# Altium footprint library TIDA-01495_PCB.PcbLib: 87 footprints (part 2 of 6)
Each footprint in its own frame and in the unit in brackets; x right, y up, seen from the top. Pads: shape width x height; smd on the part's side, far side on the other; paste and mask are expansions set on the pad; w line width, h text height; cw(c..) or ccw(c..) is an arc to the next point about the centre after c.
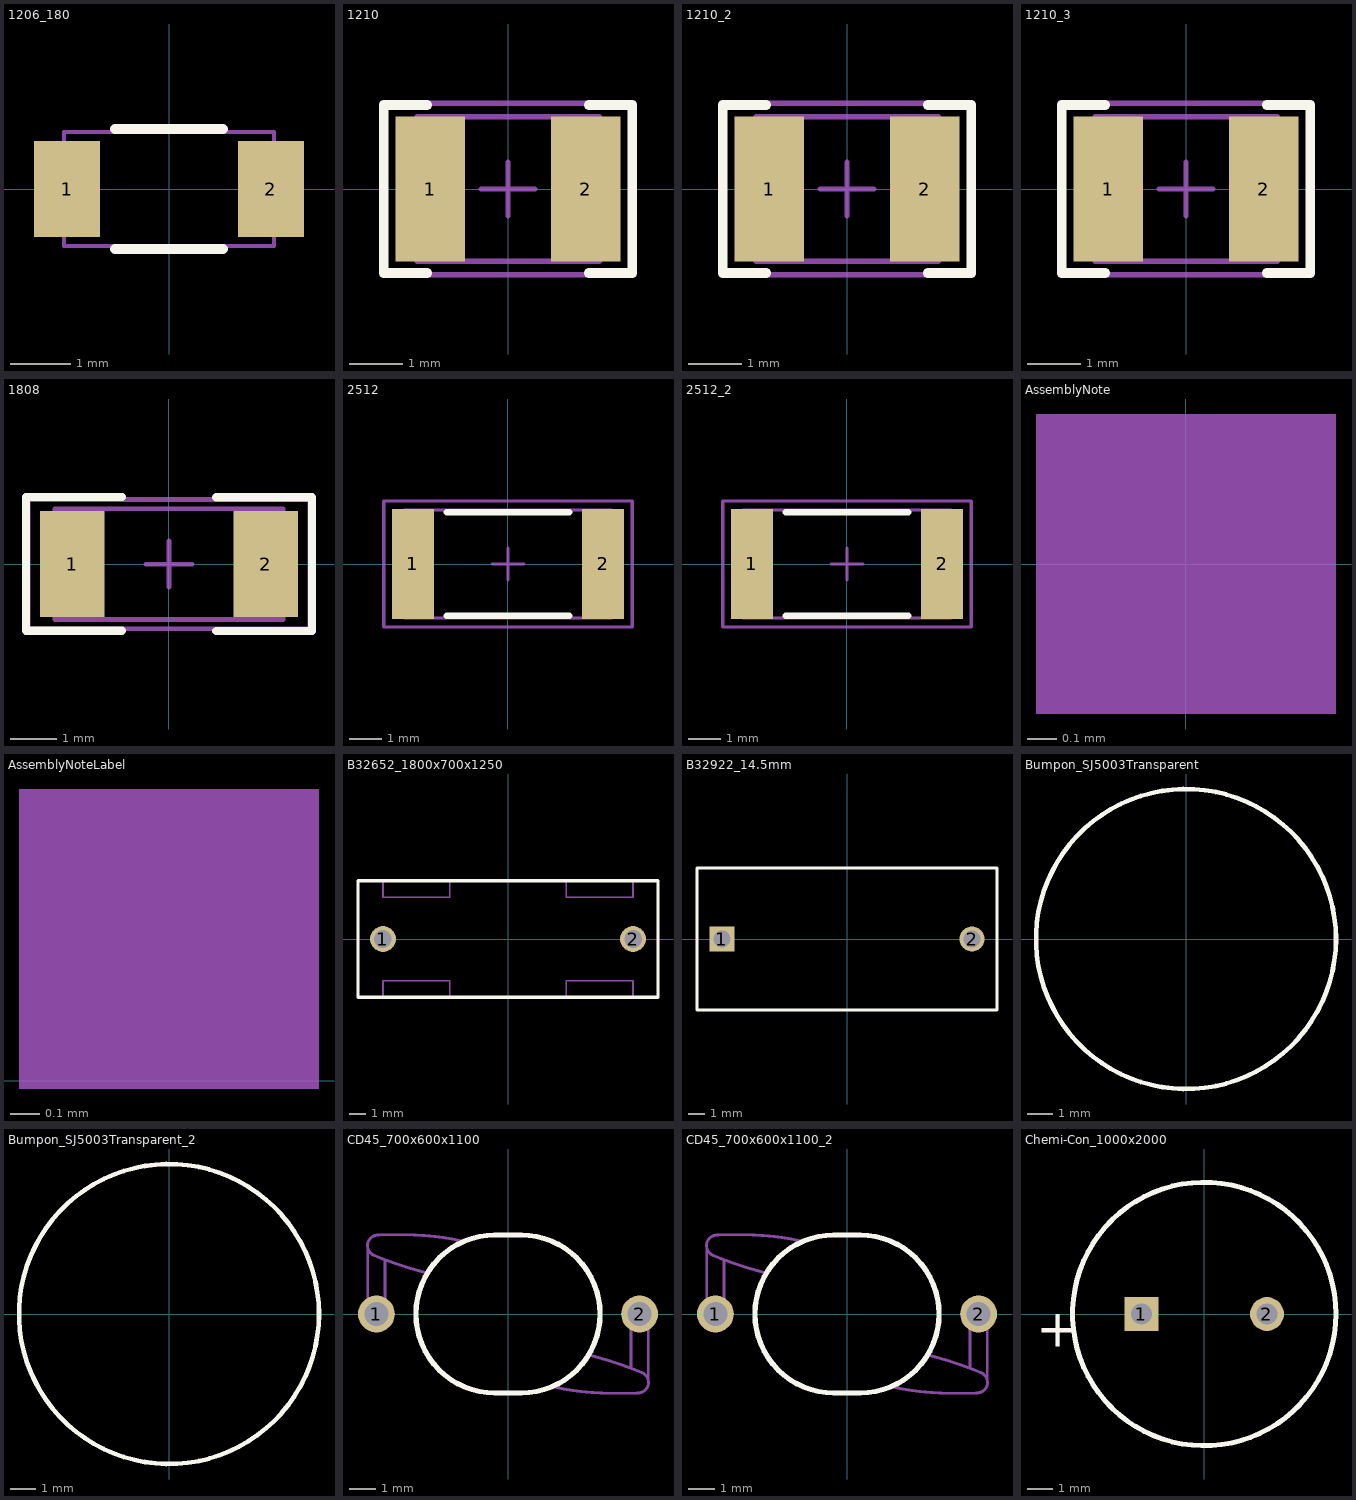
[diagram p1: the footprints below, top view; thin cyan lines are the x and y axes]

## 1206_180 [mm] "1206_180"
height 1.8
pads (2):
  rect 1.1x1.6 smd: 1(-1.7,0) 2(1.7,0)
Top Overlay:
  lines w0.17: -0.9,-1 0.9,-1 ; -0.9,1 0.9,1
Mechanical 5:
  lines w0.07: -1.75,-0.95 1.75,-0.95 1.75,0.95 -1.75,0.95 -1.75,-0.95
  text ".Designator" at 0.996,0.329 h0.81
3D body: height 1.8, standoff 0, extent -1.749,-0.949 -1.301,0.949
3D body: height 1.8, standoff 0, extent -1.299,-0.949 1.299,0.949
3D body: height 1.8, standoff 0, extent 1.301,-0.949 1.749,0.949

## 1210 [mm] "1210 from SM-752 data"
height 1.35
pads (2):
  rect 1.3x2.7 smd: 1(-1.45,0) 2(1.45,0)
Top Overlay:
  lines w0.178: -1.511,-1.568 -2.316,-1.568 -2.316,1.568 -1.511,1.568 ; 1.511,-1.568 2.316,-1.568 2.316,1.568 1.511,1.568
Mechanical 5:
  lines w0.1: -1.7,-1.35 -1.7,1.35 1.7,1.35 1.7,-1.35 -1.7,-1.35
  text ".Designator" at 1.198,0.346 h0.76
Mechanical 13:
  lines w0.1: -1.2,-1.35 -1.2,1.35 ; 1.2,-1.35 1.2,1.35 ; -1.7,-1.35 1.7,-1.35 1.7,1.35 -1.7,1.35 -1.7,-1.35
Mechanical 15:
  lines w0.1: -0.5,0 0.5,0 ; 0,-0.5 0,0.5 ; -2.35,-1.6 2.35,-1.6 2.35,1.6 -2.35,1.6 -2.35,-1.6
3D body: height 1.35, standoff 0, extent 1.201,-1.349 1.699,1.349
3D body: height 1.35, standoff 0, extent -1.199,-1.349 1.199,1.349
3D body: height 1.35, standoff 0, extent -1.699,-1.349 -1.201,1.349

## 1210_2 [mm]
pads (2):
  rect 1.3x2.7 smd: 1(-1.45,0) 2(1.45,0)
Top Overlay:
  lines w0.178: -1.511,-1.568 -2.316,-1.568 -2.316,1.568 -1.511,1.568 ; 1.511,-1.568 2.316,-1.568 2.316,1.568 1.511,1.568
Mechanical 5:
  lines w0.1: -1.7,-1.35 1.7,-1.35 1.7,1.35 -1.7,1.35 -1.7,-1.35
  text ".Designator" at 1.24,0.45 h0.76
Mechanical 13:
  lines w0.1: -1.2,-1.35 -1.2,1.35 ; 1.2,-1.35 1.2,1.35 ; -1.7,-1.35 -1.7,1.35 1.7,1.35 1.7,-1.35 -1.7,-1.35
Mechanical 15:
  lines w0.1: -0.5,0 0.5,0 ; 0,-0.5 0,0.5 ; -2.35,-1.6 -2.35,1.6 2.35,1.6 2.35,-1.6 -2.35,-1.6
3D body: height 1.35, standoff 0, extent -1.699,-1.349 -1.201,1.349
3D body: height 1.35, standoff 0, extent -1.199,-1.349 1.199,1.349
3D body: height 1.35, standoff 0, extent 1.201,-1.349 1.699,1.349

## 1210_3 [mm]
pads (2):
  rect 1.3x2.7 smd: 1(-1.45,0) 2(1.45,0)
Top Overlay:
  lines w0.178: -1.511,-1.568 -2.316,-1.568 -2.316,1.568 -1.511,1.568 ; 1.511,-1.568 2.316,-1.568 2.316,1.568 1.511,1.568
Mechanical 5:
  lines w0.1: -1.7,-1.35 1.7,-1.35 1.7,1.35 -1.7,1.35 -1.7,-1.35
  text ".Designator" at -1.177,-0.4 h0.89
Mechanical 13:
  lines w0.1: -1.2,-1.35 -1.2,1.35 ; 1.2,-1.35 1.2,1.35 ; -1.7,-1.35 -1.7,1.35 1.7,1.35 1.7,-1.35 -1.7,-1.35
Mechanical 15:
  lines w0.1: -0.5,0 0.5,0 ; 0,-0.5 0,0.5 ; -2.35,-1.6 -2.35,1.6 2.35,1.6 2.35,-1.6 -2.35,-1.6
3D body: height 1.35, standoff 0, extent -1.699,-1.349 -1.201,1.349
3D body: height 1.35, standoff 0, extent -1.199,-1.349 1.199,1.349
3D body: height 1.35, standoff 0, extent 1.201,-1.349 1.699,1.349

## 1808 [mm] "Chip Capacitor, Body 4.6x2.0mm, IPC Medium Density"
height 2.03
pads (2):
  rect 1.4x2.3 smd: 1(-2.1,0) 2(2.1,0)
Top Overlay:
  lines w0.178: -1.02,-1.445 -3.096,-1.445 -3.096,1.45 -1.02,1.45 ; 1.023,-1.448 3.099,-1.448 3.099,1.448 1.023,1.448
Mechanical 5:
  lines w0.1: -2.475,-1.2 -2.475,1.2 2.475,1.2 2.475,-1.2 -2.475,-1.2
  text ".Designator" at -1.875,-0.5 h1.02
Mechanical 13:
  lines w0.1: -1.975,-1.2 -1.975,1.2 ; 1.975,-1.2 1.975,1.2 ; -2.475,-1.2 2.475,-1.2 2.475,1.2 -2.475,1.2 -2.475,-1.2
Mechanical 15:
  lines w0.1: -0.5,0 0.5,0 ; 0,-0.5 0,0.5 ; -3.05,-1.4 3.05,-1.4 3.05,1.4 -3.05,1.4 -3.05,-1.4
3D body: height 2.03, standoff 0, extent -2.474,-1.199 -1.976,1.199
3D body: height 2.03, standoff 0, extent -1.974,-1.199 1.974,1.199
3D body: height 2.03, standoff 0, extent 1.976,-1.199 2.474,1.199

## 2512 [mm] "Chip Resistor, Body 6.3x3.2mm, IPC Medium Density"
height 0.71
pads (2):
  rect 1.3x3.4 smd: 1(-2.95,0) 2(2.95,0)
Top Overlay:
  lines w0.2: -1.9,-1.6 1.9,-1.6 ; -1.9,1.6 1.9,1.6
Mechanical 5:
  lines w0.1: -3.225,-1.675 -3.225,1.675 3.225,1.675 3.225,-1.675 -3.225,-1.675
  text ".Designator" at -1.85,-0.5 h1.02
Mechanical 13:
  lines w0.1: -2.463,-1.675 -2.463,1.675 ; 2.463,-1.675 2.463,1.675 ; -3.225,-1.675 -3.225,1.675 3.225,1.675 3.225,-1.675 -3.225,-1.675
Mechanical 15:
  lines w0.1: -0.5,0 0.5,0 ; 0,-0.5 0,0.5 ; -3.85,-1.95 -3.85,1.95 3.85,1.95 3.85,-1.95 -3.85,-1.95
3D body: height 0.71, standoff 0, extent 2.464,-1.674 3.224,1.674
3D body: height 0.71, standoff 0, extent -2.462,-1.674 2.462,1.674
3D body: height 0.71, standoff 0, extent -3.224,-1.674 -2.464,1.674

## 2512_2 [mm]
pads (2):
  rect 1.3x3.4 smd: 1(-2.95,0) 2(2.95,0)
Top Overlay:
  lines w0.2: -1.9,-1.6 1.9,-1.6 ; -1.9,1.6 1.9,1.6
Mechanical 5:
  lines w0.1: -3.225,-1.675 3.225,-1.675 3.225,1.675 -3.225,1.675 -3.225,-1.675
  text ".Designator" at -0.891,-0.556 h1.02
Mechanical 13:
  lines w0.1: -2.463,-1.675 -2.463,1.675 ; 2.463,-1.675 2.463,1.675 ; -3.225,-1.675 3.225,-1.675 3.225,1.675 -3.225,1.675 -3.225,-1.675
Mechanical 15:
  lines w0.1: -0.5,0 0.5,0 ; 0,-0.5 0,0.5 ; -3.85,-1.95 3.85,-1.95 3.85,1.95 -3.85,1.95 -3.85,-1.95
3D body: height 0.71, standoff 0, extent -3.224,-1.674 -2.464,1.674
3D body: height 0.71, standoff 0, extent -2.462,-1.674 2.462,1.674
3D body: height 0.71, standoff 0, extent 2.464,-1.674 3.224,1.674

## AssemblyNote [mm] "Assembly Note"
Mechanical 5:
  rectangle: -0.508,-0.508 0.508,0.508
  text ".Comment" at 1.143,-0.508 h1.02
  text ".Designator" at -4.191,-0.508 h0.89

## AssemblyNoteLabel [mm] "Assembly Note for PCB Labels"
Mechanical 5:
  rectangle: -2.794,-0.029 -1.778,0.987
  text ".Designator" at -6.477,-0.029 h0.89
  text "Install label in silkscreened box after final wash.  Text shall be 8 pt font.  Text shall be per the Label Table in the PDF schematic." at -1.143,-0.029 h1.02

## B32652_1800x700x1250 [mm] "TH, 2-Leads, Body 18x7mm, Pin Spacing 15mm"
height 12.5
pads (2):
  round 1.55 hole 1.05: 1(-7.5,0) 2(7.5,0)
Top Overlay:
  lines w0.2: -9,-3.5 9,-3.5 9,3.5 -9,3.5 -9,-3.5
Mechanical 5:
  lines w0.1: -7.5,-3.5 -7.5,-2.5 -3.5,-2.5 -3.5,-3.5 ; -7.5,3.5 -7.5,2.5 -3.5,2.5 -3.5,3.5 ; 3.5,-3.5 3.5,-2.5 7.5,-2.5 7.5,-3.5 ; 3.5,3.5 3.5,2.5 7.5,2.5 7.5,3.5 ; -9,-3.5 -9,3.5 9,3.5 9,-3.5 -9,-3.5
  text ".Designator" at -2,-0.7 h1.85
3D body: height 12.5, standoff 1, extent -9,-3.5 9,3.5
3D body: height 1, standoff -2.5, extent 7.103,-0.399 7.9,0.399
3D body: height 1, standoff -2.5, extent -7.897,-0.399 -7.1,0.399
3D body: height 1, standoff 0, extent -7.5,2.5 -3.5,3.5
3D body: height 1, standoff 0, extent 3.5,2.5 7.5,3.5
3D body: height 1, standoff 0, extent 3.5,-3.5 7.5,-2.5
3D body: height 1, standoff 0, extent -7.5,-3.5 -3.5,-2.5

## B32922_14.5mm [mm] "Epcos film capacitors, 15mm spacing"
height 14.5
pads (2):
  rect 1.5x1.5 hole 1: 1(-7.5,0)
  round 1.5 hole 1: 2(7.5,0)
Top Overlay:
  lines w0.178: -9,-4.25 0,-4.25 9,-4.25 9,0 9,4.25 0,4.25 -9,4.25 -9,0 -9,-4.25
Mechanical 5:
  lines w0.127: -9,-4.25 -9,0 -9,4.25 0,4.25 9,4.25 9,0 9,-4.25 0,-4.25 -9,-4.25
  text ".Designator" at 1.69,0.592 h1.02
3D body: height 14.5, standoff 0, extent -8.999,-4.249 8.999,4.249

## Bumpon_SJ5003Transparent [mil] "3M Hemispherical Bumpon transparent"
height 200
pads (1):
  round 1 on Mech3: 0(0,0)
Top Overlay:
  circle w7: c0,0 r228.04
Mechanical 5:
  circle w5: c0,0 r228.04
  text ".Designator" at -60,-20 h40
3D body "3M_SJ5003Transparent.stp": height 196.82, standoff 0, extent -218.5,-218.5 218.51,218.51

## Bumpon_SJ5003Transparent_2 [mil]
pads (1):
  round 1 on Mech3: 0(0,0)
Top Overlay:
  circle w7: c0,0 r228.04
Mechanical 5:
  circle w5: c0,0 r228.04
  text ".Designator" at -60,-20 h40
3D body "3M_SJ5003Transparent.stp": height 196.82, standoff 0, extent -218.5,-218.5 218.51,218.51

## CD45_700x600x1100 [mm] "TH, 2-Leads, Dia 7mm, Pin Spacing 10 mm"
height 11
pads (2):
  round 1.4 hole 0.9: 1(-5,0) 2(5,0)
Top Overlay:
  lines w0.2: -0.5,-3 cw(c-0.5,0) -0.5,3 0.5,3 cw(c0.5,0) 0.5,-3 -0.5,-3
Mechanical 5:
  drawing of 576 lines, arcs and shapes, not listed
  text ".Designator" at -1.012,-0.536 h0.89
3D body "CD45-102-N.stp": height 11, standoff -5, extent -5.34,-3.016 5.341,3.016

## CD45_700x600x1100_2 [mm]
pads (2):
  round 1.4 hole 0.9: 1(-5,0) 2(5,0)
Top Overlay:
  lines w0.2: -0.5,-3 cw(c-0.5,0) -0.5,3 0.5,3 cw(c0.5,0) 0.5,-3 -0.5,-3
Mechanical 5:
  drawing of 576 lines, arcs and shapes, not listed
  text ".Designator" at 0.318,-0.853 h0.89
3D body "CD45-102-N.stp": height 11, standoff -5, extent -5.34,-3.016 5.341,3.016

## Chemi-Con_1000x2000 [mm] "TH, 2-Leads, Body 10x20mm, Pin Spacing 5mm"
height 21.5
pads (2):
  rect 1.35x1.35 hole 0.85: 1(-2.5,0)
  round 1.35 hole 0.85: 2(2.5,0)
Top Overlay:
  circle w0.2: c0,0 r5.25
  text "+" at -6.704,-1.296 h1.5
Mechanical 5:
  lines w0.1: 5.25,-0.001 cw(c0,0) 5.25,0
  text ".Designator" at -1.484,-0.459 h1.02
  text "+" at -6.704,-1.296 h1.5
3D body: height 0, standoff -2, extent 2.203,-0.299 2.8,0.3
3D body: height 0, standoff -2.5, extent -2.797,-0.299 -2.2,0.3
3D body: height 21.5, standoff 0, extent -4.25,-4.25 4.249,4.249
3D body: height 21.5, standoff 0, extent 3.68,-2.626 5.25,2.622
3D body: height 21.5, standoff 0, extent -5.249,-5.25 4.55,5.25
